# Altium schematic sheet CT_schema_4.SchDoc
size 176 x 147 mm
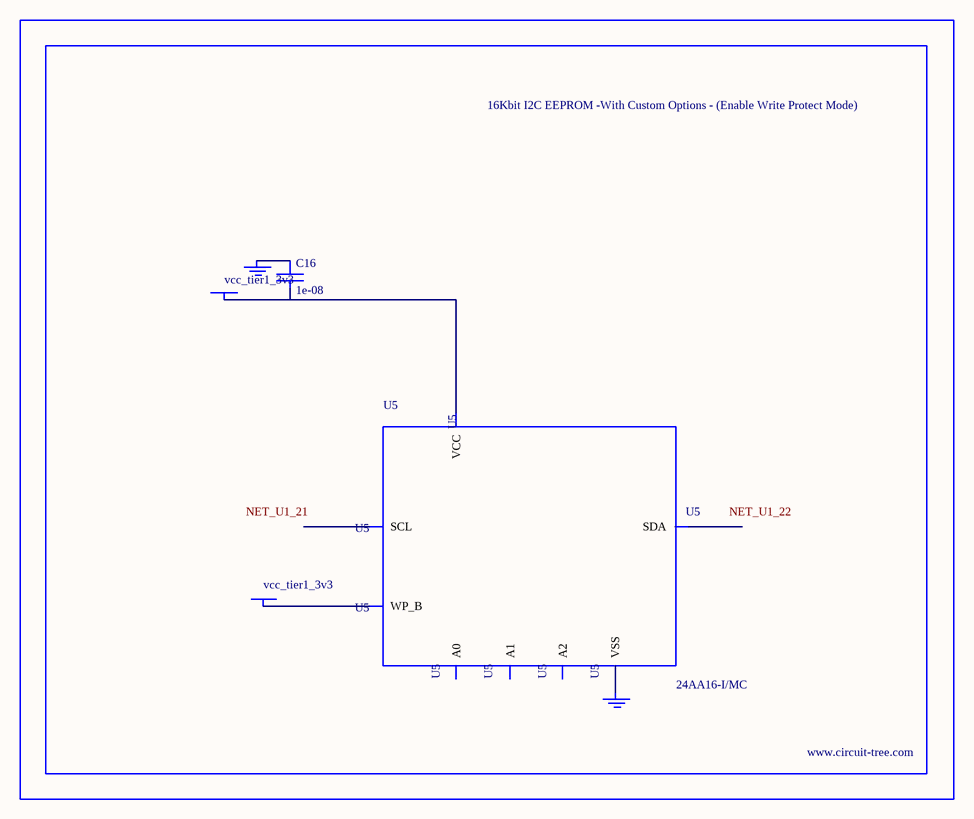
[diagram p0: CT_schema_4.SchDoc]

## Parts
BORDER3  (no value)
C16  1e-08  [C0402]
GND_INSTANCE_3_0  (no value)
GND_INSTANCE_3_1  (no value)
POWER_INSTANCE_3_0  vcc_tier1_3v3
POWER_INSTANCE_3_1  vcc_tier1_3v3
U5  24AA16-I/MC  [TDFN-8/6MM]

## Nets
NetC16_1: C16.1 GND_INSTANCE_3_0.0(GND)
NetC16_2: C16.2 POWER_INSTANCE_3_1.0(PWR) U5.8(VCC)
NetGND_INSTANCE_3_1_0: GND_INSTANCE_3_1.0(GND) U5.4(VSS)
NetPOWER_INSTANCE_3_0_0: POWER_INSTANCE_3_0.0(PWR) U5.7(WP_B)

Not connected (* = marked no-connect by the designer): U5 1(A0) 2(A1) 3(A2) 5(SDA) 6(SCL)

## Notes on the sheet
- Labels drawn without touching a wire or pin: NET_U1_21, NET_U1_22

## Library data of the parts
BORDER3 = BORDER_PAGE3
C16 = C0402C103K3RAC
GND_INSTANCE_3_0 GND_INSTANCE_3_1 = GND
POWER_INSTANCE_3_0 POWER_INSTANCE_3_1 = PWR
